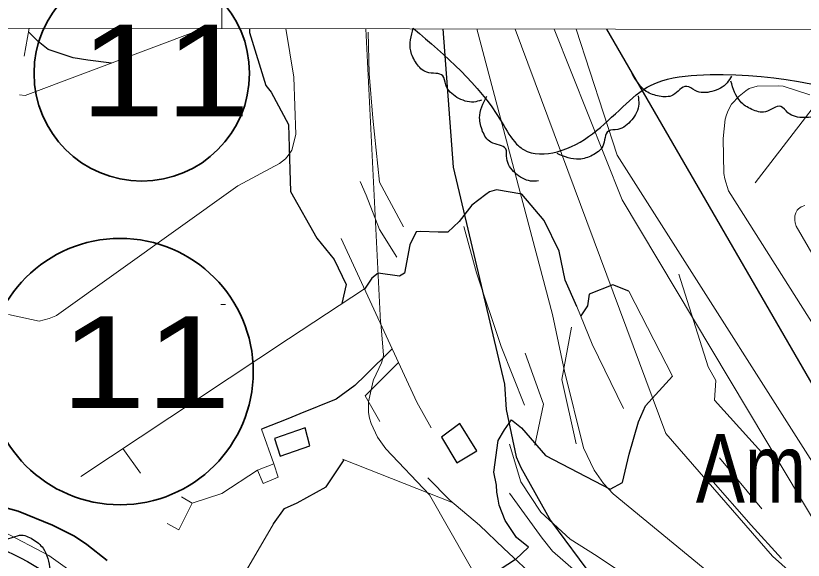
# Model space of a CAD drawing. Extents: x 483847 to 488453, y 4383581 to 4386795.
# Drawn here: x 484955 to 485127.1, y 4386330.2 to 4386449.2 of the extents above; entities that cross this region are included whole.
import ezdxf
from ezdxf.enums import TextEntityAlignment as Align

# ---------------------------------------------------------------- set-up
doc = ezdxf.new("R2010")
doc.units = 0
doc.header["$LTSCALE"] = 3.8
doc.linetypes.add('LONG_DASHED', pattern=[7.5, 6, -1.5])
doc.linetypes.add('MEDIUM_DASHED', pattern=[4.5, 3, -1.5])
for name, color, linetype, lineweight in [('1', 7, 'Continuous', 13), ('13', 7, 'Continuous', 25), ('21', 7, 'Continuous', 25), ('25', 7, 'LONG_DASHED', 25), ('27', 7, 'Continuous', 25), ('47', 7, 'Continuous', 35), ('48', 7, 'MEDIUM_DASHED', 25), ('51', 7, 'Continuous', 13), ('6', 7, 'Continuous', 35), ('7', 7, 'Continuous', 13), ('8', 7, 'Continuous', 25), ('9', 7, 'Continuous', 13)]:
    doc.layers.add(name, color=color, linetype=linetype, lineweight=lineweight)
doc.layers.add('31', color=7, linetype='Continuous')

msp = doc.modelspace()

# ---------------------------------------------------------------- linework, layer by layer
at = {"layer": '1'}
msp.add_line((485000, 4386446.37), (485000, 4386517.75), dxfattribs=at)
msp.add_lwpolyline([(484105.5, 4386448.1), (487681.9, 4386441.2), (487678, 4384129), (484100.5, 4384135.8)], close=True, dxfattribs=at)
at = {"layer": '21'}
msp.add_lwpolyline([(485012.77, 4386352.91), (485019.22, 4386355.14), (485018.23, 4386359.06), (485011.49, 4386356.73)], close=True, dxfattribs=at)
at = {"layer": '25'}
for points in [[(484975.89, 4386438.82), (484970.74, 4386439.45), (484967.49, 4386439.96), (484962.05, 4386441.74), (484959.85, 4386443.53), (484957.72, 4386445.65)], [(485006.03, 4386446.36), (485006.02, 4386445.49), (485009.6, 4386433.9), (485010.8, 4386432.43), (485014.6, 4386425.41), (485014.85, 4386415.48), (485014.99, 4386410.72), (485020.74, 4386400.57), (485024.55, 4386395.88), (485027.16, 4386390.44), (485026.26, 4386386.26)], [(485077.59, 4386385.61), (485075, 4386391.33), (485073.75, 4386397.71), (485070.41, 4386404.43), (485065.54, 4386410.14), (485060.03, 4386411.14), (485058.47, 4386410.67), (485057.68, 4386410.05), (485054.61, 4386407.72), (485051.84, 4386404.21), (485049.37, 4386401.86), (485047.25, 4386401.86), (485043.41, 4386401.98), (485042.45, 4386401.94), (485041.07, 4386399.1), (485039.9, 4386392.93), (485038.81, 4386392.26), (485034.13, 4386392.92), (485032.75, 4386391.83), (485031.18, 4386389.43)], [(485088.96, 4386388.95), (485085.42, 4386390.31), (485080.25, 4386388.3), (485079.91, 4386385.74), (485078.44, 4386383.55)], [(485037.23, 4386376.38), (485031.37, 4386370.63), (485029.08, 4386368.36), (485024.97, 4386365.33), (485017.01, 4386362.12), (485014.41, 4386361.07), (485008.69, 4386358.82)], [(485064.2, 4386330.34), (485067.04, 4386332.99), (485064.41, 4386335.1), (485061.95, 4386338.82), (485060.63, 4386342.19), (485060.41, 4386343.53), (485060.07, 4386345.05), (485060.06, 4386346.58), (485059.46, 4386349.42), (485060.39, 4386356.32), (485061.8, 4386358.65), (485063.34, 4386360.83), (485065.51, 4386359.06), (485070.77, 4386353.04), (485084.87, 4386345.7), (485087.54, 4386347.13), (485089.03, 4386353.32), (485091.09, 4386360.41), (485092.56, 4386363.89), (485098.47, 4386370.4)], [(485011.29, 4386338.14), (485013.72, 4386341.43), (485016.43, 4386342.67), (485022.79, 4386346.2), (485026.7, 4386352.11)], [(485064.2, 4386330.34), (485051.81, 4386322.32), (485041.79, 4386313.2), (485025.21, 4386302.16)]]:
    msp.add_lwpolyline(points, dxfattribs=at)
at = {"layer": '27'}
for points in [[(485056.77, 4386430.7), (485055.04, 4386430.29), (485051.39, 4386431.32), (485048.93, 4386434.07), (485048.27, 4386436.02), (485044.81, 4386436.8), (485042.54, 4386438.75), (485041.28, 4386441.49), (485041.82, 4386446.42)], [(485041.82, 4386446.41), (485060.9, 4386426.36), (485064, 4386421.59), (485065.91, 4386419.92), (485073.3, 4386419.44), (485087.61, 4386429.23), (485093.82, 4386434), (485103.84, 4386436.15), (485190.9, 4386411.09), (485205.69, 4386408.7), (485212.13, 4386413.24), (485223.34, 4386423.5), (485240.04, 4386445.93)], [(485111.36, 4386435.98), (485110.42, 4386434.47), (485107.12, 4386432.6), (485103.43, 4386432.8), (485101.59, 4386433.71), (485098.59, 4386431.81), (485095.61, 4386431.58), (485092.77, 4386432.63), (485089.66, 4386436.49)], [(485132.18, 4386429.13), (485130.9, 4386427.89), (485127.25, 4386426.88), (485123.72, 4386427.97), (485122.15, 4386429.3), (485118.78, 4386428.18), (485115.83, 4386428.68), (485113.34, 4386430.38), (485111.25, 4386434.88)], [(485069.24, 4386413.06), (485067.47, 4386413.03), (485064.11, 4386414.79), (485062.27, 4386417.99), (485062.04, 4386420.03), (485058.81, 4386421.52), (485057, 4386423.89), (485056.34, 4386426.84), (485057.89, 4386431.55)], [(485090.96, 4386431.62), (485091.11, 4386429.85), (485089.58, 4386426.38), (485086.52, 4386424.32), (485084.5, 4386423.95), (485083.23, 4386420.63), (485080.99, 4386418.66), (485078.09, 4386417.8), (485073.28, 4386419.02)], [(484700.18, 4386195.41), (484750.6, 4386216.22), (484776.67, 4386228), (484779.62, 4386225.05), (484778.78, 4386222.11), (484767.42, 4386211.17), (484761.53, 4386201.49), (484762.8, 4386188.87), (484767, 4386176.67), (484776.67, 4386171.2), (484788.03, 4386171.62), (484796.86, 4386188.03), (484811.16, 4386231.78), (484821.67, 4386263.34), (484838.91, 4386286.48), (484868.77, 4386322.24), (484889.8, 4386336.55), (484901.57, 4386337.81), (484912.09, 4386332.76), (484919.24, 4386332.76), (484928.07, 4386336.55), (484929.75, 4386336.55), (484935.22, 4386336.55), (484960.45, 4386328.13), (484990.73, 4386305.83), (485012.18, 4386295.73), (485037.41, 4386278.06), (485058.02, 4386260.39), (485061.38, 4386254.92), (485060.54, 4386248.19), (485059.28, 4386246.09), (485054.23, 4386246.93), (485039.93, 4386264.18), (485027.32, 4386274.7), (485013.02, 4386281.43), (485005.87, 4386280.17), (485002.5, 4386272.17), (485003.77, 4386259.55), (485026.05, 4386241.46), (485035.31, 4386235.15), (485042.88, 4386225.89), (485046.66, 4386209.06), (485049.61, 4386199.81), (485055.91, 4386190.97), (485066.85, 4386188.45), (485075.26, 4386188.87), (485091.66, 4386197.7), (485095.86, 4386206.54), (485096.29, 4386218.74), (485100.07, 4386226.31), (485108.9, 4386233.89), (485118.57, 4386233.89), (485133.71, 4386224.63)], [(484942.37, 4386336.27), (484943.79, 4386337.35), (484947.54, 4386337.91), (484950.91, 4386336.41), (484952.3, 4386334.9), (484955.79, 4386335.61), (484958.65, 4386334.76), (484960.93, 4386332.77), (484962.46, 4386328.05)]]:
    msp.add_spline(points, degree=3, dxfattribs=at)
at = {"layer": '47', "lineweight": 13}
msp.add_lwpolyline([(485007.78, 4386349.81), (485011.34, 4386351.22), (485012.29, 4386348.32), (485009.02, 4386346.91)], close=True, dxfattribs=at)
msp.add_lwpolyline([(484991.18, 4386343.98), (484993.48, 4386342.66), (484990.57, 4386336.83), (484988.06, 4386338.22)], dxfattribs=at)
at = {"layer": '48'}
msp.add_lwpolyline([(485047.97, 4386357.07), (485051.39, 4386351.42), (485055.76, 4386354.03), (485052.03, 4386360.03)], close=True, dxfattribs=at)
at = {"layer": '51'}
for p, q in [((484956.78, 4386440.3), (484957.87, 4386446.46)), ((485142.2, 4386446.1), (485116.58, 4386412.6)), ((485088.96, 4386388.95), (485098.48, 4386370.37)), ((485011.34, 4386351.22), (485008.69, 4386358.82)), ((484978.39, 4386354.55), (484982.25, 4386349.22)), ((485108.73, 4386352.54), (485117.99, 4386341.36)), ((485026.37, 4386352.22), (485050.53, 4386342.67)), ((485000.42, 4386319.41), (485011.29, 4386338.14))]:
    msp.add_line(p, q, dxfattribs=at)
for points in [[(484955.76, 4386431.85), (484957.04, 4386431.72), (484995.98, 4386446.38)], [(485039.67, 4386403.05), (485034.45, 4386412.75), (485033.03, 4386426.8), (485032.22, 4386436.51), (485031.98, 4386445.54)], [(485038.27, 4386396.36), (485034.44, 4386402.46), (485031.53, 4386409.95), (485030.2, 4386412.92)], [(485052.91, 4386403.11), (485055.65, 4386392.95), (485061.05, 4386376.84), (485066.17, 4386364.08)], [(485026.06, 4386400.47), (485042.64, 4386364.69), (485045.73, 4386359.06)], [(485099.89, 4386392.66), (485106.27, 4386372.43), (485107.98, 4386369.4), (485107.65, 4386365.13), (485118.57, 4386353.08)], [(485031.15, 4386389.5), (485014.6, 4386378.53), (484969.18, 4386348.44)], [(485087.78, 4386363.29), (485080.95, 4386377.35), (485077.59, 4386385.61)], [(485077.43, 4386355.57), (485074.34, 4386369.66), (485076.4, 4386381.06)], [(485066.28, 4386375.39), (485070.27, 4386364.25), (485068.42, 4386355.3)], [(485038.61, 4386373.39), (485031.31, 4386366.06), (485034.54, 4386360.49)], [(485095.64, 4386321.93), (485081.99, 4386331.07), (485076.13, 4386334.73), (485069.72, 4386340.66), (485065.38, 4386347.27), (485062.87, 4386355.49)], [(485007.78, 4386349.81), (484999.97, 4386344.76), (484993.48, 4386342.66)], [(485044.99, 4386348.17), (485049.8, 4386343.28), (485056.28, 4386337.81), (485061.64, 4386332.73), (485069.1, 4386325.74), (485078.74, 4386315.42), (485088.57, 4386303.92)], [(485122.31, 4386330.5), (485115.71, 4386337.84), (485106.84, 4386347.88)], [(485104.59, 4386301.98), (485092.83, 4386313.92), (485086.91, 4386320.06), (485077.38, 4386327.73), (485072.27, 4386332.15), (485070.03, 4386335), (485062.86, 4386344.79)]]:
    msp.add_lwpolyline(points, dxfattribs=at)
at = {"layer": '6'}
msp.add_lwpolyline([(484950.32, 4386342.24), (484955.52, 4386340.89), (484963.01, 4386337.82), (484967.78, 4386335.39), (484970.48, 4386333.62), (484974.91, 4386330.09)], dxfattribs=at)
for centre, radius in [((484982.5, 4386436.57), 23.55), ((484977.77, 4386371.38), 29.1)]:
    msp.add_circle(centre, radius, dxfattribs=at)
at = {"layer": '7'}
msp.add_line((484999.8, 4386386.03), (485000.8, 4386386.03), dxfattribs=at)
at = {"layer": '8'}
for points in [[(485048.32, 4386446.28), (485050.58, 4386416.07), (485061.81, 4386368.6), (485062.14, 4386363.09), (485064.34, 4386352.74), (485065.36, 4386350.42), (485071.84, 4386338.85), (485081.23, 4386326.16), (485094.58, 4386312.24), (485103.32, 4386300.2), (485107.57, 4386295.7), (485110.42, 4386293.42), (485112.27, 4386292.28), (485127.37, 4386284.97)], [(485084.04, 4386446.21), (485134.06, 4386359.92), (485146.97, 4386342.39), (485156.63, 4386333.56), (485165.58, 4386327.63), (485177.02, 4386322.95), (485225.81, 4386310.24), (485228.47, 4386308.93), (485230.46, 4386307.5), (485238.27, 4386299.85), (485243.73, 4386293.13), (485259.47, 4386279.08), (485277.76, 4386269.18), (485281.27, 4386266.13), (485285.15, 4386261.7), (485320.46, 4386180.26), (485356.58, 4386136.4)]]:
    msp.add_lwpolyline(points, dxfattribs=at)
at = {"layer": '9'}
for points in [[(484953.38, 4386383.83), (484960.06, 4386382.43), (484960.08, 4386382.42), (484962.29, 4386382.96), (484963.7, 4386383.6), (484963.85, 4386383.64), (485003.46, 4386411.95), (485012.62, 4386416.86), (485013.89, 4386417.89), (485014.53, 4386418.62), (485015.27, 4386419.81), (485016.19, 4386423.19), (485015.71, 4386435.76), (485013.99, 4386446.35)], [(485031.47, 4386446.31), (485034.69, 4386382.21), (485034.73, 4386382), (485035.34, 4386375.04), (485035.28, 4386374.44), (485035.25, 4386374.32), (485035.21, 4386374.25), (485035.2, 4386374.22), (485034.9, 4386373.33), (485033.18, 4386369.61), (485033.08, 4386369.35), (485032.03, 4386364.8), (485032.08, 4386362.44), (485032.26, 4386361.22), (485032.64, 4386360.02), (485034.04, 4386357.07), (485035.85, 4386354.52), (485045.35, 4386344.48), (485062.31, 4386314.81), (485062.31, 4386314.7), (485068.95, 4386305.15), (485069.96, 4386303.47), (485070.14, 4386303.23)], [(485202.12, 4386252.61), (485183.03, 4386262.17), (485172.13, 4386269.22), (485160.54, 4386279.02), (485146.5, 4386288.48), (485127.37, 4386305.46), (485111.77, 4386323.09), (485085.49, 4386344.69), (485083.4, 4386346.91), (485081.34, 4386349.86), (485079.07, 4386354.73), (485074.86, 4386371.45), (485072.29, 4386383.86), (485055.76, 4386446.27)], [(485064.13, 4386446.25), (485097.01, 4386357.83), (485120.33, 4386331.03), (485139.99, 4386313.52), (485167.53, 4386296.94), (485207.17, 4386279.69), (485213.86, 4386275.01), (485247.44, 4386236.88), (485249.1, 4386234.36), (485254.11, 4386223.4), (485269.44, 4386196.02)], [(485138.52, 4386323.63), (485087.47, 4386408.91), (485072.6, 4386446.23)], [(485077.44, 4386446.22), (485086.43, 4386418.67), (485139.83, 4386334.74)], [(485128.47, 4386431.88), (485122.64, 4386433.73), (485121.68, 4386433.81), (485117.01, 4386433.76), (485115.27, 4386433.23), (485114.49, 4386432.73), (485113.08, 4386431.61), (485111.42, 4386429.81), (485110.67, 4386428.48), (485110.26, 4386427.47), (485110.03, 4386426.54), (485109.54, 4386422.32), (485109.71, 4386414.65), (485109.9, 4386413.54), (485110.74, 4386410.89), (485142.7, 4386360.37)], [(485127.42, 4386407.7), (485126.64, 4386407.39), (485126.01, 4386406.95), (485125.74, 4386406.66), (485125.42, 4386406.07), (485125.25, 4386405.44), (485125.2, 4386405.1), (485125.22, 4386404.49), (485125.31, 4386403.92), (485125.53, 4386403.14), (485140.96, 4386376.61)], [(484974.14, 4386322.64), (484962.2, 4386331.18), (484952.24, 4386336.44)]]:
    msp.add_lwpolyline(points, dxfattribs=at)

# ---------------------------------------------------------------- texts
at = {"layer": '13', "width": 1.25}
for p in [(484987.57, 4386427.19), (484983.38, 4386363.43)]:
    msp.add_text('11', height=20, dxfattribs=at).set_placement(p, align=Align.CENTER)
at = {"layer": '31', "width": 0.8}
msp.add_text('Am', height=15, dxfattribs=at).set_placement((485115.64, 4386342.77), align=Align.CENTER)

doc.saveas('drawing.dxf')
